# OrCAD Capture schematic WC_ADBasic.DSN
size A; company: mycompany; note: line1; note: line 2
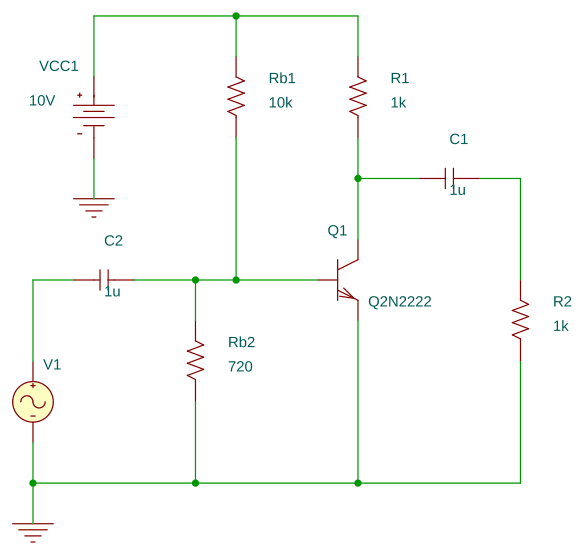
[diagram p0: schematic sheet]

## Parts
C1  1u  [RAD/CK05]
C2  1u  [RAD/CK05]
Q1  Q2N2222  [TO18]
R1  1k  [AX/RC05]
R2  1k  [AX/RC05]
Rb1  10k  [AX/RC05]
Rb2  720  [AX/RC05]
V1  VAC
VCC1  VDC

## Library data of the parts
C1 C2 = C
Q1 = Q2N2222
R1 R2 Rb1 = R
Rb2 = R: TOLERANCE: 5%
V1 = VAC
VCC1 = VDC: DC: 10V

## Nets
0: Q1.1(e) R2.1 Rb2.1 V1.2(-) VCC1.1(-)
N00216: C2.2 Q1.2(b) Rb1.1 Rb2.2
N00248: R1.2 Rb1.2 VCC1.0(+)
N00272: C1.1 Q1.3(c) R1.1
N00326: C1.2 R2.2
N00453: C2.1 V1.1(+)
